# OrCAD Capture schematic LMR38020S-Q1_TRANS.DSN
size D; title: LMR38020S-Q1: LMR38020 SIMPLE SWITCHER®; rev: 1.0; note: Datasheet: SNVSC40A                  EVM: SNVU787; note: Synchronous Step Down Converter
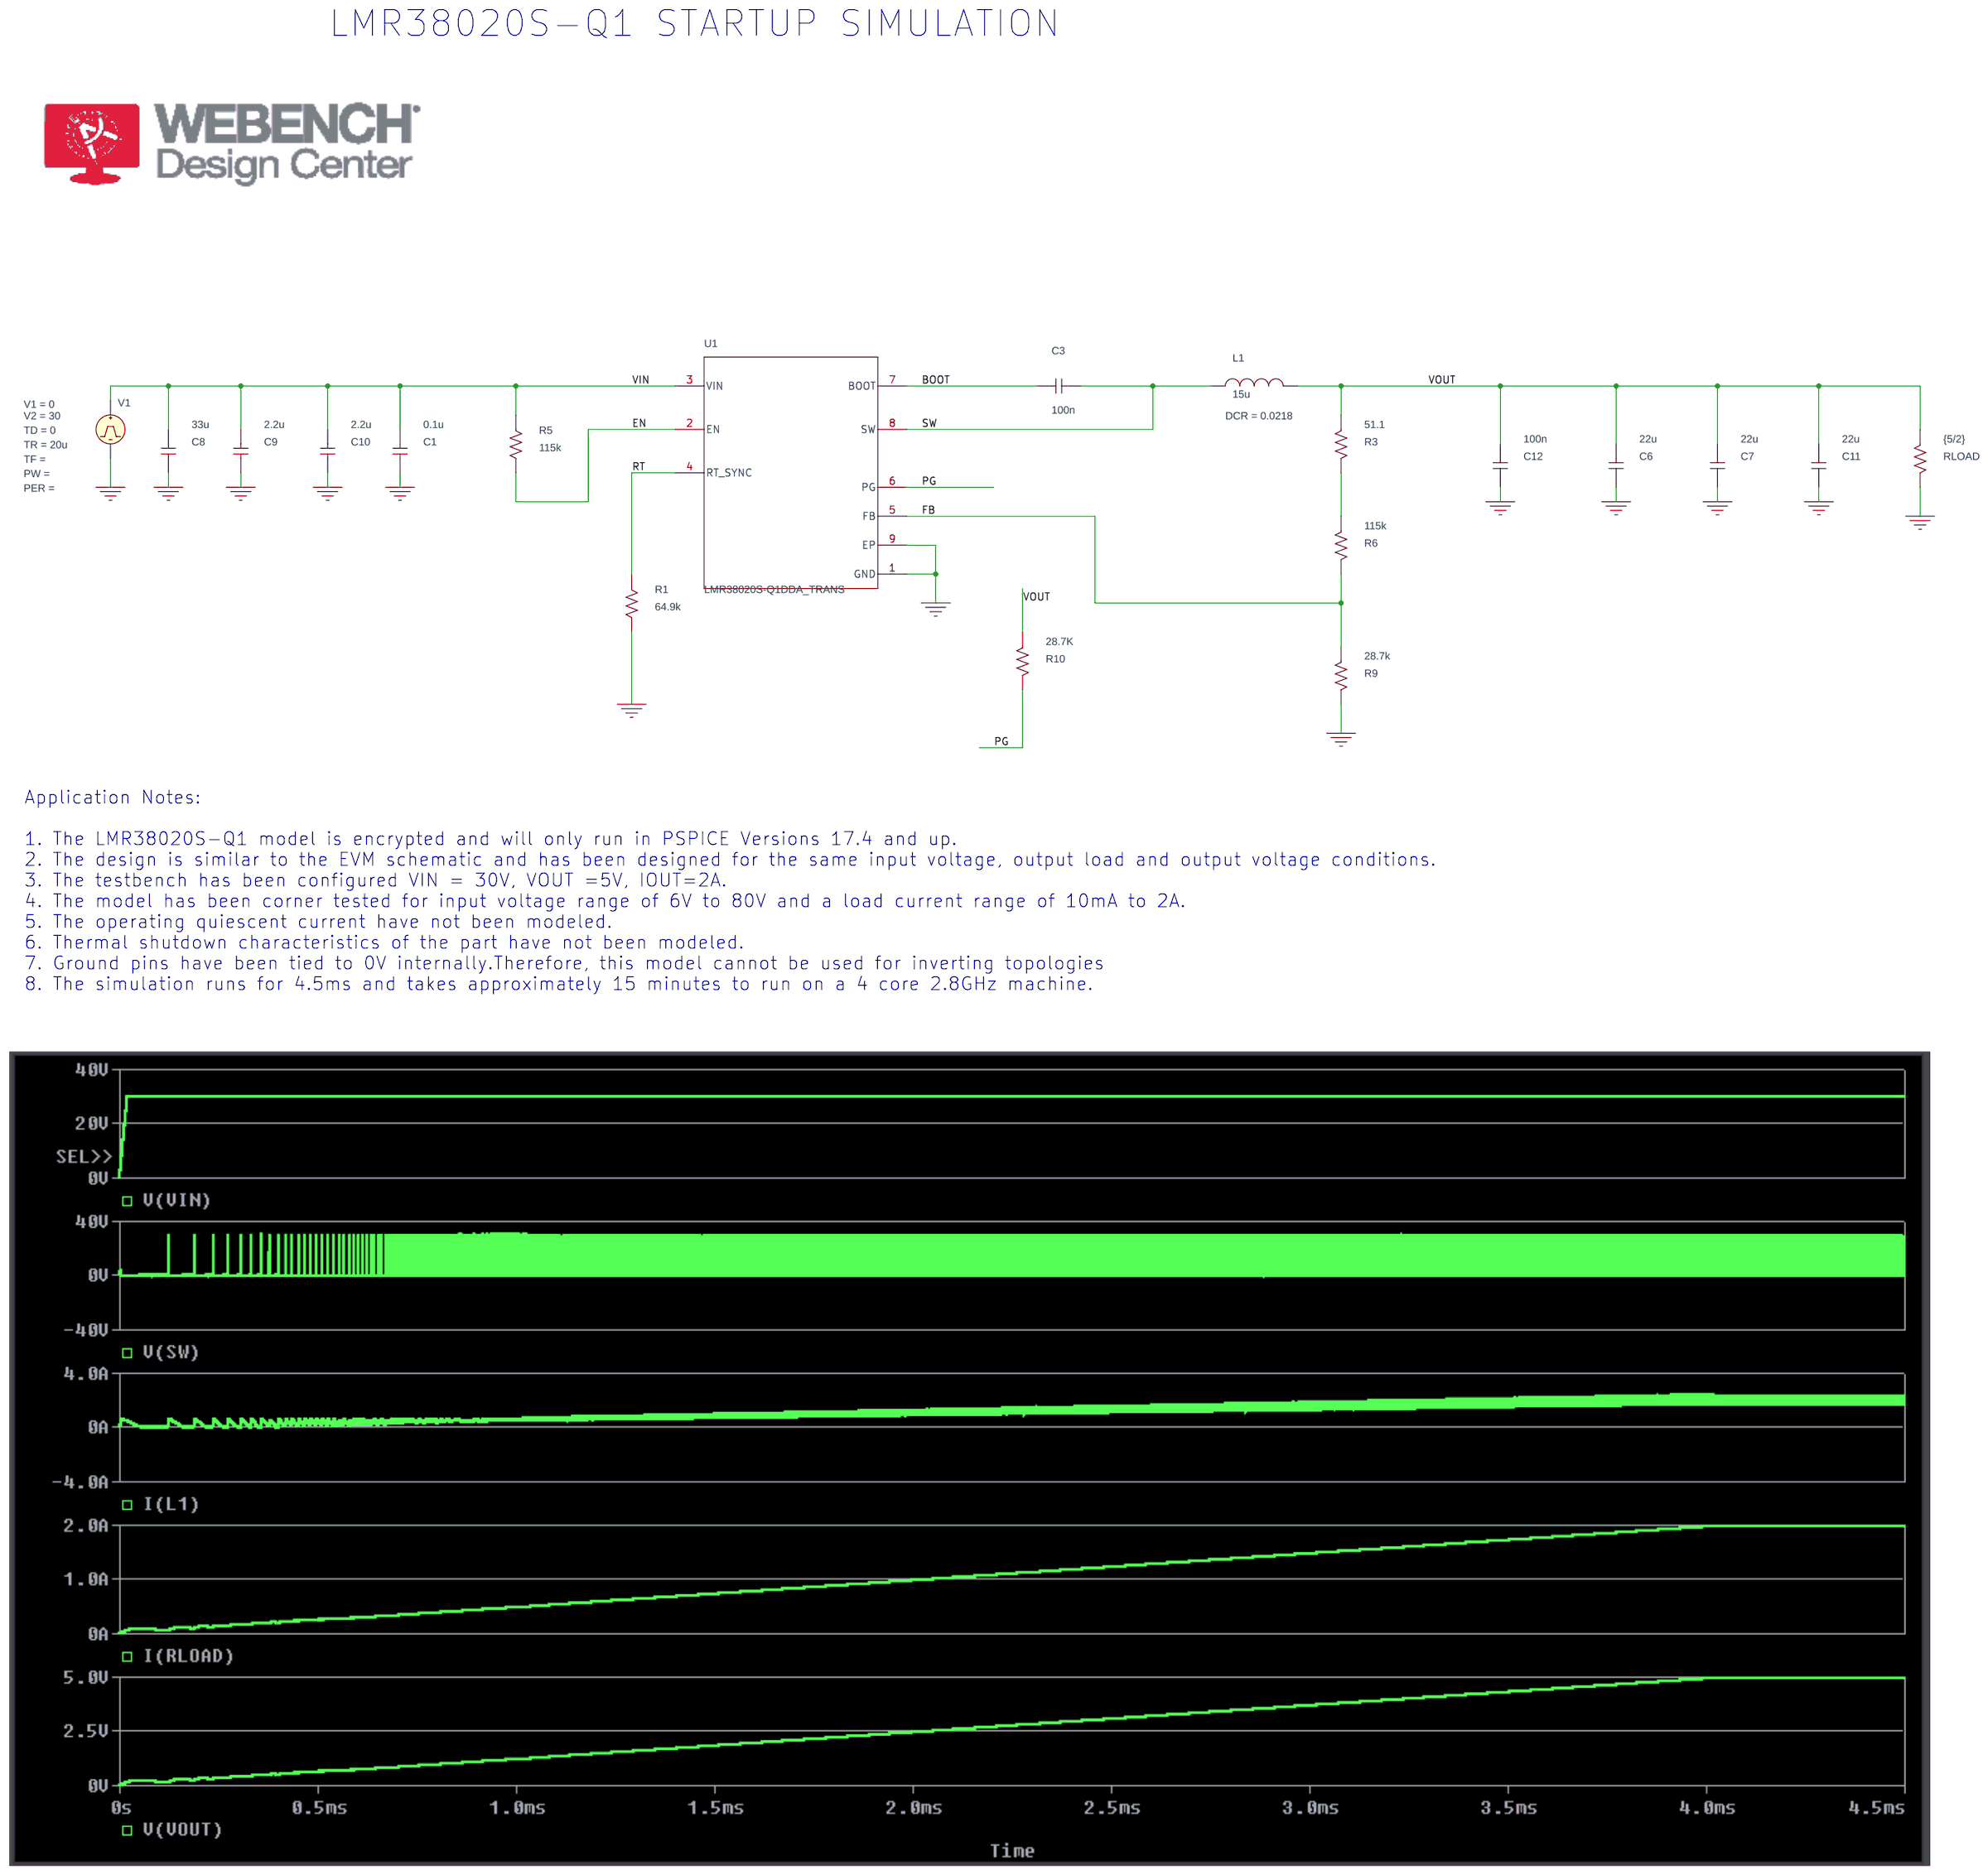
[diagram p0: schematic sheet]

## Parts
C1  0.1u  [RAD/CK05]
C3  100n  [RAD/CK05]
C6  22u  [RAD/CK05]
C7  22u  [RAD/CK05]
C8  33u  [RAD/CK05]
C9  2.2u  [RAD/CK05]
C10  2.2u  [RAD/CK05]
C11  22u  [RAD/CK05]
C12  100n  [RAD/CK05]
L1  15u  [DISC/.350x.175/LS.200x.100/.034]
R1  64.9k  [AX/RC05]
R3  51.1  [AX/RC05]
R5  115k  [AX/RC05]
R6  115k  [AX/RC05]
R9  28.7k  [AX/RC05]
R10  28.7K  [AX/RC05]
RLOAD  {5/2}  [AX/RC05]
U1  LMR38020S-Q1DDA_TRANS  [DDA0008J-IPC_A]
V1  VPULSE

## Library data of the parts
C1 C3 C6-C12 = c
L1 = L: DCR: 0.0218; IC: 0
R1 R3 R5 R6 R9 R10 RLOAD = r
U1 = LMR38020S-Q1DDA_TRANS
V1 = VPULSE: TD: 0; TR: 20u; V1: 0; V2: 30

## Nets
VIN: C1.1 C8.1 C9.1 C10.1 R5.1 U1.3(VIN) V1.1(+)
0: C1.2 C6.2 C7.2 C8.2 C9.2 C10.2 C11.2 C12.2 R1.2 R9.2 RLOAD.2 U1.1(GND) U1.9(EP) V1.2(-)
BOOT: C3.1 U1.7(BOOT)
EN: R5.2 U1.2(EN)
FB: R6.2 R9.1 U1.5(FB)
PG: R10.2 U1.6(PG)
RT: R1.1 U1.4(RT_SYNC)
SW: C3.2 L1.1 U1.8(SW)
VOUT: C6.1 C7.1 C11.1 C12.1 L1.2 R3.1 R10.1 RLOAD.1
N53703: R3.2 R6.1

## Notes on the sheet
- LMR38020S-Q1 STARTUP SIMULATION
- Application Notes:
  1. The LMR38020S-Q1 model is encrypted and will only run in PSPICE Versions 17.4 and up.
  2. The design is similar to the EVM schematic and has been designed for the same input voltage, output load and output voltage conditions.
  3. The testbench has been configured VIN = 30V, VOUT =5V, IOUT=2A.
  4. The model has been corner tested for input voltage range of 6V to 80V and a load current range of 10mA to 2A.
  5. The operating quiescent current have not been modeled.
  6. Thermal shutdown characteristics of the part have not been modeled.
  7. Ground pins have been tied to 0V internally.Therefore, this model cannot be used for inverting topologies
  8. The simulation runs for 4.5ms and takes approximately 15 minutes to run on a 4 core 2.8GHz machine.
